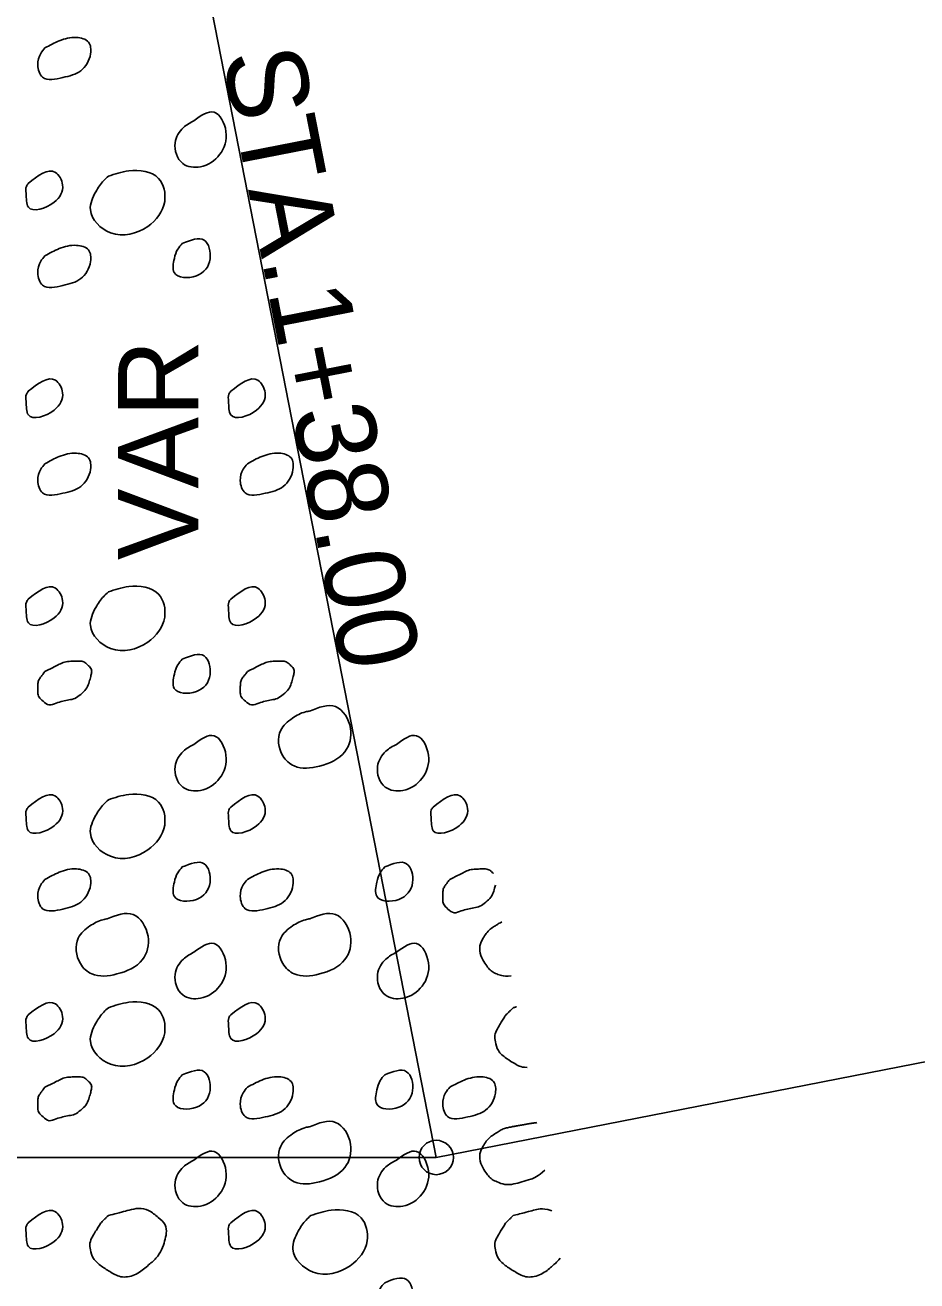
# Model space of a CAD drawing. Extents: x 0 to 2765, y 0 to 220.
# Drawn here: x 160.8 to 176.38, y 145.04 to 166.97 of the extents above; entities that cross this region are included whole.
import ezdxf

# ---------------------------------------------------------------- set-up
doc = ezdxf.new("R2010")
doc.units = 0
for name, color, linetype in [('MT_P_PCB', 7, 'Continuous'), ('MT_P_Stop_Line', 7, 'Continuous'), ('MT_P_Work_Area', 7, 'Continuous'), ('XS_P_Finished_Grade', 7, 'Continuous')]:
    doc.layers.add(name, color=color, linetype=linetype)

msp = doc.modelspace()

# ---------------------------------------------------------------- linework, layer by layer
at = {"layer": 'MT_P_PCB'}
msp.add_line((167.983, 147.197), (163.663, 169.279), dxfattribs=at)
msp.add_circle((167.983, 147.197), 0.3, dxfattribs=at)
at = {"layer": 'MT_P_Stop_Line'}
for points in [[(161.151, 166.576), (161.401, 166.701), (161.702, 166.759), (161.912, 166.678), (161.947, 166.474), (161.776, 166.178), (161.462, 166.058), (161.111, 166.064), (161.025, 166.279), (161.077, 166.479), (161.151, 166.576)], [(163.753, 165.304), (164.105, 165.455), (164.312, 165.117), (164.201, 164.712), (163.867, 164.499), (163.557, 164.559), (163.423, 164.918), (163.569, 165.185), (163.753, 165.304)], [(160.859, 164.209), (161.334, 164.402), (161.46, 164.184), (161.311, 163.881), (160.861, 163.797), (160.822, 164.037), (160.826, 164.158), (160.859, 164.209)], [(162.258, 164.335), (162.614, 164.429), (163.135, 164.297), (163.242, 163.894), (162.947, 163.459), (162.298, 163.349), (161.944, 163.747), (162.039, 164.065), (162.177, 164.258), (162.258, 164.335)], [(163.549, 163.162), (163.931, 163.218), (164.035, 162.89), (163.795, 162.596), (163.408, 162.652), (163.411, 162.898), (163.469, 163.061), (163.549, 163.162)], [(161.151, 162.946), (161.401, 163.071), (161.702, 163.128), (161.912, 163.047), (161.947, 162.844), (161.776, 162.547), (161.462, 162.427), (161.111, 162.433), (161.025, 162.649), (161.077, 162.849), (161.151, 162.946)], [(160.859, 160.579), (161.334, 160.771), (161.46, 160.553), (161.311, 160.251), (160.861, 160.166), (160.822, 160.406), (160.826, 160.527), (160.859, 160.579)], [(164.395, 160.579), (164.87, 160.771), (164.996, 160.553), (164.847, 160.251), (164.397, 160.166), (164.357, 160.406), (164.362, 160.527), (164.395, 160.579)], [(161.151, 159.315), (161.401, 159.44), (161.702, 159.498), (161.912, 159.417), (161.947, 159.213), (161.776, 158.917), (161.462, 158.797), (161.111, 158.803), (161.025, 159.018), (161.077, 159.218), (161.151, 159.315)], [(164.687, 159.315), (164.937, 159.44), (165.237, 159.498), (165.448, 159.417), (165.482, 159.213), (165.312, 158.917), (164.998, 158.797), (164.647, 158.803), (164.561, 159.018), (164.612, 159.218), (164.687, 159.315)], [(160.859, 156.948), (161.334, 157.141), (161.46, 156.923), (161.311, 156.62), (160.861, 156.536), (160.822, 156.776), (160.826, 156.897), (160.859, 156.948)], [(162.258, 157.074), (162.614, 157.168), (163.135, 157.036), (163.242, 156.633), (162.947, 156.198), (162.298, 156.088), (161.944, 156.486), (162.039, 156.804), (162.177, 156.997), (162.258, 157.074)], [(164.395, 156.948), (164.87, 157.141), (164.996, 156.923), (164.847, 156.62), (164.397, 156.536), (164.357, 156.776), (164.362, 156.897), (164.395, 156.948)], [(163.549, 155.901), (163.931, 155.957), (164.035, 155.629), (163.795, 155.335), (163.408, 155.391), (163.411, 155.637), (163.469, 155.8), (163.549, 155.901)], [(165.773, 154.995), (166.227, 155.071), (166.487, 154.691), (166.39, 154.285), (165.944, 154.032), (165.504, 154.035), (165.305, 154.213), (165.268, 154.658), (165.473, 154.871), (165.699, 154.98), (165.782, 154.997)], [(163.753, 154.413), (164.105, 154.564), (164.312, 154.225), (164.201, 153.82), (163.867, 153.608), (163.557, 153.667), (163.423, 154.026), (163.569, 154.294), (163.753, 154.413)], [(167.289, 154.413), (167.641, 154.564), (167.848, 154.225), (167.737, 153.82), (167.403, 153.608), (167.092, 153.667), (166.959, 154.026), (167.105, 154.294), (167.289, 154.413)], [(160.859, 153.318), (161.334, 153.51), (161.46, 153.292), (161.311, 152.99), (160.861, 152.905), (160.822, 153.145), (160.826, 153.266), (160.859, 153.318)], [(162.258, 153.444), (162.614, 153.537), (163.135, 153.405), (163.242, 153.003), (162.947, 152.568), (162.298, 152.457), (161.944, 152.855), (162.039, 153.174), (162.177, 153.366), (162.258, 153.444)], [(164.395, 153.318), (164.87, 153.51), (164.996, 153.292), (164.847, 152.99), (164.397, 152.905), (164.357, 153.145), (164.362, 153.266), (164.395, 153.318)], [(167.931, 153.318), (168.406, 153.51), (168.532, 153.292), (168.382, 152.99), (167.932, 152.905), (167.893, 153.145), (167.897, 153.266), (167.931, 153.318)], [(161.151, 152.054), (161.401, 152.179), (161.702, 152.237), (161.912, 152.156), (161.947, 151.953), (161.776, 151.656), (161.462, 151.536), (161.111, 151.542), (161.025, 151.758), (161.077, 151.958), (161.151, 152.054)], [(163.549, 152.271), (163.931, 152.327), (164.035, 151.998), (163.795, 151.704), (163.408, 151.761), (163.411, 152.007), (163.469, 152.17), (163.549, 152.271)], [(164.687, 152.054), (164.937, 152.179), (165.237, 152.237), (165.448, 152.156), (165.482, 151.953), (165.312, 151.656), (164.998, 151.536), (164.647, 151.542), (164.561, 151.758), (164.612, 151.958), (164.687, 152.054)], [(167.085, 152.271), (167.467, 152.327), (167.571, 151.998), (167.331, 151.704), (166.944, 151.761), (166.947, 152.007), (167.005, 152.17), (167.085, 152.271)], [(162.237, 151.365), (162.692, 151.441), (162.951, 151.061), (162.854, 150.654), (162.408, 150.402), (161.968, 150.404), (161.769, 150.583), (161.732, 151.028), (161.937, 151.241), (162.163, 151.349), (162.246, 151.367)], [(165.773, 151.365), (166.227, 151.441), (166.487, 151.061), (166.39, 150.654), (165.944, 150.402), (165.504, 150.404), (165.305, 150.583), (165.268, 151.028), (165.473, 151.241), (165.699, 151.349), (165.782, 151.367)], [(163.753, 150.783), (164.105, 150.933), (164.312, 150.595), (164.201, 150.19), (163.867, 149.978), (163.557, 150.037), (163.423, 150.396), (163.569, 150.663), (163.753, 150.783)], [(167.289, 150.783), (167.641, 150.933), (167.848, 150.595), (167.737, 150.19), (167.403, 149.978), (167.092, 150.037), (166.959, 150.396), (167.105, 150.663), (167.289, 150.783)], [(160.859, 149.688), (161.334, 149.88), (161.46, 149.662), (161.311, 149.359), (160.861, 149.275), (160.822, 149.515), (160.826, 149.636), (160.859, 149.688)], [(162.258, 149.813), (162.614, 149.907), (163.135, 149.775), (163.242, 149.373), (162.947, 148.938), (162.298, 148.827), (161.944, 149.225), (162.039, 149.543), (162.177, 149.736), (162.258, 149.813)], [(164.395, 149.688), (164.87, 149.88), (164.996, 149.662), (164.847, 149.359), (164.397, 149.275), (164.357, 149.515), (164.362, 149.636), (164.395, 149.688)], [(163.549, 148.64), (163.931, 148.696), (164.035, 148.368), (163.795, 148.074), (163.408, 148.13), (163.411, 148.376), (163.469, 148.54), (163.549, 148.64)], [(167.085, 148.64), (167.467, 148.696), (167.571, 148.368), (167.331, 148.074), (166.944, 148.13), (166.947, 148.376), (167.005, 148.54), (167.085, 148.64)], [(164.687, 148.424), (164.937, 148.549), (165.237, 148.606), (165.448, 148.525), (165.482, 148.322), (165.312, 148.025), (164.998, 147.905), (164.647, 147.911), (164.561, 148.127), (164.612, 148.327), (164.687, 148.424)], [(168.222, 148.424), (168.472, 148.549), (168.773, 148.606), (168.984, 148.525), (169.018, 148.322), (168.847, 148.025), (168.534, 147.905), (168.182, 147.911), (168.097, 148.127), (168.148, 148.327), (168.222, 148.424)], [(165.773, 147.735), (166.227, 147.81), (166.487, 147.43), (166.39, 147.024), (165.944, 146.771), (165.504, 146.774), (165.305, 146.952), (165.268, 147.397), (165.473, 147.61), (165.699, 147.719), (165.782, 147.736)], [(163.753, 147.152), (164.105, 147.303), (164.312, 146.965), (164.201, 146.56), (163.867, 146.347), (163.557, 146.406), (163.423, 146.765), (163.569, 147.033), (163.753, 147.152)], [(167.289, 147.152), (167.641, 147.303), (167.848, 146.965), (167.737, 146.56), (167.403, 146.347), (167.092, 146.406), (166.959, 146.765), (167.105, 147.033), (167.289, 147.152)], [(160.859, 146.057), (161.334, 146.25), (161.46, 146.031), (161.311, 145.729), (160.861, 145.645), (160.822, 145.885), (160.826, 146.005), (160.859, 146.057)], [(164.395, 146.057), (164.87, 146.25), (164.996, 146.031), (164.847, 145.729), (164.397, 145.645), (164.357, 145.885), (164.362, 146.005), (164.395, 146.057)], [(165.794, 146.183), (166.15, 146.276), (166.671, 146.145), (166.778, 145.742), (166.482, 145.307), (165.834, 145.196), (165.48, 145.595), (165.575, 145.913), (165.713, 146.105), (165.794, 146.183)], [(167.085, 145.01), (167.467, 145.066), (167.571, 144.737), (167.331, 144.443), (166.944, 144.5), (166.947, 144.746), (167.005, 144.909), (167.085, 145.01)]]:
    msp.add_spline(points, degree=3, dxfattribs=at)
for points, degree in [([(161.151, 155.685), (161.234, 155.727), (161.317, 155.768), (161.401, 155.81), (161.492, 155.855), (161.602, 155.864), (161.702, 155.867), (161.775, 155.869), (161.846, 155.852), (161.912, 155.786), (161.973, 155.726), (161.964, 155.646), (161.947, 155.583), (161.917, 155.478), (161.878, 155.371), (161.776, 155.286), (161.676, 155.203), (161.57, 155.191), (161.462, 155.166), (161.35, 155.14), (161.221, 155.073), (161.111, 155.172), (161.038, 155.237), (161.023, 155.314), (161.025, 155.388), (161.027, 155.454), (161.035, 155.533), (161.077, 155.588), (161.101, 155.621), (161.126, 155.653), (161.151, 155.685)], 3), ([(164.687, 155.685), (164.77, 155.727), (164.853, 155.768), (164.937, 155.81), (165.028, 155.855), (165.138, 155.864), (165.237, 155.867), (165.311, 155.869), (165.382, 155.852), (165.448, 155.786), (165.509, 155.726), (165.5, 155.646), (165.482, 155.583), (165.453, 155.478), (165.414, 155.371), (165.312, 155.286), (165.212, 155.203), (165.106, 155.191), (164.998, 155.166), (164.886, 155.14), (164.757, 155.073), (164.647, 155.172), (164.574, 155.237), (164.559, 155.314), (164.561, 155.388), (164.563, 155.454), (164.571, 155.533), (164.612, 155.588), (164.637, 155.621), (164.662, 155.653), (164.687, 155.685)], 3), ([(168.222, 152.054), (168.306, 152.096), (168.389, 152.138), (168.472, 152.179), (168.564, 152.225), (168.674, 152.234), (168.773, 152.237), (168.847, 152.239), (168.918, 152.222), (168.984, 152.156), (168.984, 152.156), (168.985, 152.155), (168.985, 152.155)], 3), ([(169.019, 151.956), (169.019, 151.955), (169.019, 151.954), (169.018, 151.953), (168.989, 151.848), (168.95, 151.741), (168.847, 151.656), (168.747, 151.573), (168.642, 151.561), (168.534, 151.536), (168.421, 151.51), (168.293, 151.443), (168.182, 151.542), (168.11, 151.607), (168.095, 151.683), (168.097, 151.758), (168.098, 151.824), (168.107, 151.902), (168.148, 151.958), (168.173, 151.99), (168.198, 152.022), (168.222, 152.054)], 3), ([(169.295, 150.367), (169.208, 150.361), (169.121, 150.37), (169.04, 150.404), (168.955, 150.44), (168.893, 150.502), (168.841, 150.583), (168.754, 150.716), (168.729, 150.901), (168.804, 151.028), (168.854, 151.111), (168.922, 151.185), (169.009, 151.241), (169.05, 151.267), (169.09, 151.292), (169.131, 151.312)], 3), ([(169.571, 148.769), (169.5, 148.772), (169.432, 148.79), (169.37, 148.827), (169.212, 148.92), (169.046, 149.06), (169.016, 149.225), (168.997, 149.328), (169.05, 149.448), (169.111, 149.543), (169.154, 149.612), (169.192, 149.681), (169.249, 149.736), (169.276, 149.762), (169.303, 149.788), (169.33, 149.813)], 3), ([(169.33, 149.813), (169.349, 149.818), (169.368, 149.824), (169.388, 149.829)], 2), ([(161.151, 148.424), (161.234, 148.466), (161.317, 148.507), (161.401, 148.549), (161.492, 148.594), (161.602, 148.603), (161.702, 148.606), (161.775, 148.608), (161.846, 148.591), (161.912, 148.525), (161.973, 148.465), (161.964, 148.385), (161.947, 148.322), (161.917, 148.217), (161.878, 148.11), (161.776, 148.025), (161.676, 147.942), (161.57, 147.93), (161.462, 147.905), (161.35, 147.879), (161.221, 147.812), (161.111, 147.911), (161.038, 147.976), (161.023, 148.053), (161.025, 148.127), (161.027, 148.193), (161.035, 148.272), (161.077, 148.327), (161.101, 148.36), (161.126, 148.392), (161.151, 148.424)], 3), ([(169.881, 146.978), (169.76, 146.864), (169.626, 146.814), (169.48, 146.771), (169.339, 146.73), (169.18, 146.714), (169.04, 146.774), (168.955, 146.81), (168.893, 146.872), (168.841, 146.952), (168.754, 147.086), (168.729, 147.271), (168.804, 147.397), (168.854, 147.481), (168.922, 147.555), (169.009, 147.61), (169.083, 147.657), (169.153, 147.701), (169.235, 147.719), (169.262, 147.725), (169.29, 147.73), (169.317, 147.736)], 3), ([(169.309, 147.735), (169.452, 147.759), (169.595, 147.786), (169.738, 147.807)], 2), ([(162.258, 146.183), (162.377, 146.214), (162.496, 146.245), (162.614, 146.276), (162.787, 146.321), (162.962, 146.289), (163.135, 146.145), (163.269, 146.032), (163.278, 145.866), (163.242, 145.742), (163.198, 145.585), (163.099, 145.437), (162.947, 145.307), (162.757, 145.145), (162.493, 145.081), (162.298, 145.196), (162.141, 145.289), (161.975, 145.429), (161.944, 145.595), (161.925, 145.697), (161.979, 145.817), (162.039, 145.913), (162.082, 145.981), (162.121, 146.05), (162.177, 146.105), (162.204, 146.131), (162.231, 146.157), (162.258, 146.183)], 3), ([(169.33, 146.183), (169.448, 146.214), (169.567, 146.245), (169.686, 146.276), (169.792, 146.304), (169.899, 146.302), (170.005, 146.264)], 3), ([(170.148, 145.438), (170.11, 145.392), (170.067, 145.349), (170.018, 145.307), (169.828, 145.145), (169.564, 145.081), (169.37, 145.196), (169.212, 145.289), (169.046, 145.429), (169.016, 145.595), (168.997, 145.697), (169.05, 145.817), (169.111, 145.913), (169.154, 145.981), (169.192, 146.05), (169.249, 146.105), (169.276, 146.131), (169.303, 146.157), (169.33, 146.183)], 3)]:
    msp.add_open_spline(points, degree=degree, dxfattribs=at)
at = {"layer": 'MT_P_Work_Area'}
for p, q in [((167.983, 147.197), (228.829, 159.103)), ((99.983, 147.197), (167.983, 147.197))]:
    msp.add_line(p, q, dxfattribs=at)

# ---------------------------------------------------------------- texts
at = {"layer": 'MT_P_PCB'}
for s, p in [(' STA. ', (164.138, 166.961)), ('1+38.00', (165.045, 162.323))]:
    msp.add_text(s, height=1.4, rotation=281.0711, dxfattribs=at).set_placement(p)
at = {"layer": 'XS_P_Finished_Grade'}
msp.add_text('VAR', height=1.4, rotation=90, dxfattribs=at).set_placement((163.829, 157.632))

doc.saveas('drawing.dxf')
